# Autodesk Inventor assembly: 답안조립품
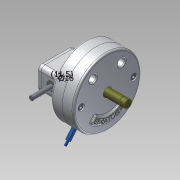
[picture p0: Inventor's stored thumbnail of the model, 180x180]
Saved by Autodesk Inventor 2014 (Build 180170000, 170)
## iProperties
Created: 2015-04
Part Number: 답안조립품
Document SubType Name: Assembly
Designer: Administrator
Mass: 3964.99 g
Surface Area: 3333.71 cm^2
Volume: 1140.85 cm^3
Density: 3.47547 g/cm^3
Author: Administrator
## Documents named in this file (15)
- C:\Documents and Settings\Administrator\바탕 화면\350406V1043\답안조립품.iam
- C:\Documents and Settings\Administrator\바탕 화면\350406V1043\스프링.ipt
- C:\Documents and Settings\Administrator\바탕 화면\350406V1043\본체.ipt
- C:\Documents and Settings\Administrator\바탕 화면\350406V1043\커버.ipt
- C:\Documents and Settings\Administrator\바탕 화면\350406V1043\커버2.ipt
- C:\Documents and Settings\Administrator\바탕 화면\350406V1043\M 10 x 35.ipt
- C:\Documents and Settings\Administrator\바탕 화면\350406V1043\M 5 x 12.ipt
- C:\Documents and Settings\Administrator\바탕 화면\350406V1043\부시.ipt
- C:\Documents and Settings\Administrator\바탕 화면\350406V1043\슬라이더3.ipt
- C:\Documents and Settings\Administrator\바탕 화면\350406V1043\축.ipt
- C:\Documents and Settings\Administrator\바탕 화면\350406V1043\베어링62_22.ipt
- C:\Documents and Settings\Administrator\바탕 화면\350406V1043\멈춤링.ipt
- C:\Documents and Settings\Administrator\바탕 화면\350406V1043\슬라이더2.ipt
- C:\Documents and Settings\Administrator\바탕 화면\350406V1043\평행핀.ipt
- C:\Documents and Settings\Administrator\바탕 화면\350406V1043\슬라이더.ipt
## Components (5 placed, 3 different names)
1. M 10 x 35:1
2. M 10 x 35:2
3. M 5 x 12:1
4. M 5 x 12:2
5. KS B 1320 B B 5 x  20:1 — 플러쉬:1
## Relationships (1: Flush 1)
- 플러쉬:1 [Flush]: KS B 1320 B B 5 x  20:1
